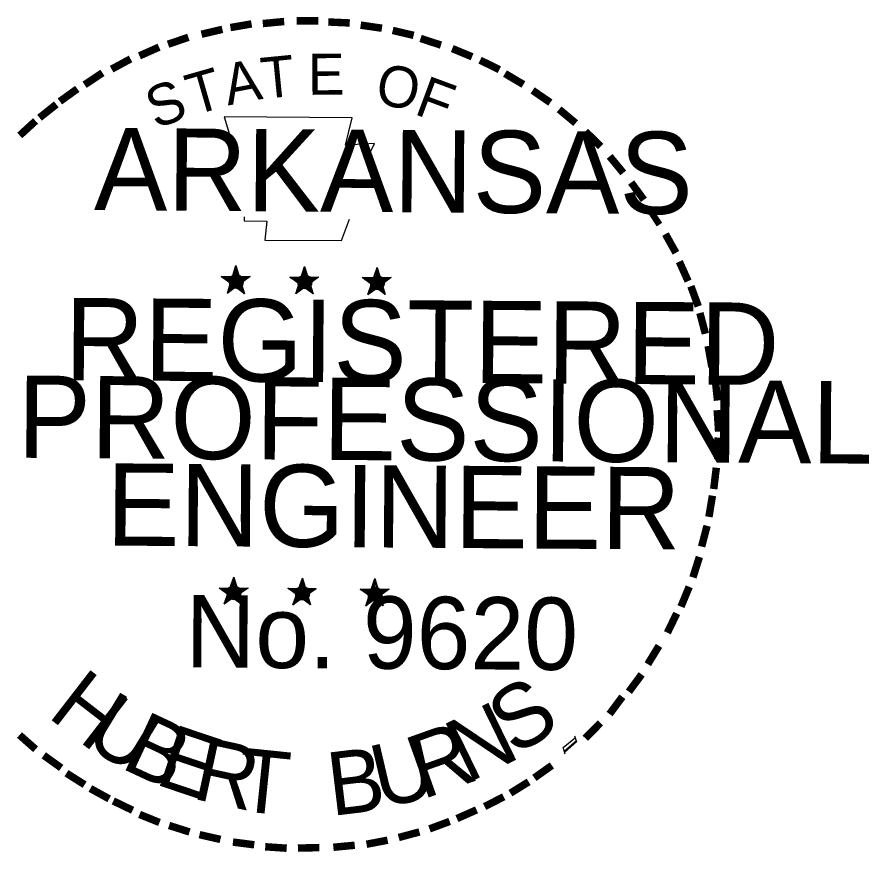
# Model space of a CAD drawing. Extents: x 309389.3 to 309420.2, y 336441.4 to 336461.2.
# Drawn here: x 309416.82 to 309420.237, y 336442.278 to 336445.626 of the extents above; entities that cross this region are included whole.
import ezdxf

# ---------------------------------------------------------------- set-up
doc = ezdxf.new("R2010")
doc.units = 0
doc.layers.add('R_Temp Easement', color=7, linetype='Continuous')

msp = doc.modelspace()

# ---------------------------------------------------------------- linework, layer by layer
at = {"layer": 'R_Temp Easement'}
for p, q in [((309417.6985, 336444.63), (309417.6904, 336444.5853)), ((309417.6985, 336444.63), (309417.6904, 336444.5893)), ((309417.6985, 336444.63), (309417.6944, 336444.5893)), ((309417.6985, 336444.5669), (309417.6985, 336444.63)), ((309417.6985, 336444.63), (309417.7087, 336444.5853)), ((309417.6985, 336444.63), (309417.7067, 336444.5893)), ((309417.6985, 336444.63), (309417.7005, 336444.5893)), ((309417.9732, 336444.626), (309417.9651, 336444.5832)), ((309417.9732, 336444.626), (309417.9651, 336444.5853)), ((309417.9732, 336444.626), (309417.9671, 336444.5853)), ((309417.9732, 336444.5669), (309417.9732, 336444.626)), ((309417.9732, 336444.626), (309417.9834, 336444.5832)), ((309417.9732, 336444.626), (309417.9814, 336444.5853)), ((309417.9732, 336444.626), (309417.9753, 336444.5853)), ((309418.2642, 336444.6219), (309418.2541, 336444.5832)), ((309418.2642, 336444.6219), (309418.2602, 336444.5812)), ((309418.2642, 336444.6219), (309418.2602, 336444.5812)), ((309418.2642, 336444.5608), (309418.2642, 336444.6219)), ((309418.2642, 336444.6219), (309418.2765, 336444.5812)), ((309418.2642, 336444.6219), (309418.2724, 336444.5812)), ((309418.2642, 336444.6219), (309418.2683, 336444.5812)), ((309417.6395, 336444.5853), (309417.6985, 336444.5669)), ((309417.6395, 336444.5853), (309417.6822, 336444.5832)), ((309417.6395, 336444.5853), (309417.6822, 336444.5812)), ((309417.6395, 336444.5853), (309417.6782, 336444.5751)), ((309417.6395, 336444.5853), (309417.6782, 336444.569)), ((309417.6395, 336444.5853), (309417.6782, 336444.5669)), ((309417.6395, 336444.5853), (309417.6782, 336444.5608)), ((309417.6639, 336444.5181), (309417.6985, 336444.5669)), ((309417.6639, 336444.5181), (309417.6782, 336444.5649)), ((309417.7555, 336444.5853), (309417.6985, 336444.5669)), ((309417.7331, 336444.5161), (309417.6985, 336444.5669)), ((309417.7555, 336444.5853), (309417.7026, 336444.5812)), ((309417.7555, 336444.5853), (309417.7087, 336444.5771)), ((309417.7555, 336444.5853), (309417.7087, 336444.573)), ((309417.7331, 336444.5161), (309417.7087, 336444.5649)), ((309417.7331, 336444.5161), (309417.7148, 336444.5669)), ((309417.7555, 336444.5853), (309417.7168, 336444.573)), ((309417.7555, 336444.5853), (309417.7229, 336444.569)), ((309417.7555, 336444.5853), (309417.725, 336444.5669)), ((309417.9142, 336444.5832), (309417.9732, 336444.5669)), ((309417.9142, 336444.5832), (309417.957, 336444.5812)), ((309417.9142, 336444.5832), (309417.957, 336444.5771)), ((309417.9142, 336444.5832), (309417.957, 336444.5751)), ((309417.9142, 336444.5832), (309417.9549, 336444.5669)), ((309417.9142, 336444.5832), (309417.9549, 336444.5649)), ((309417.9142, 336444.5832), (309417.9549, 336444.5588)), ((309417.9386, 336444.5161), (309417.9732, 336444.5669)), ((309418.0302, 336444.5832), (309417.9732, 336444.5669)), ((309418.0078, 336444.5161), (309417.9732, 336444.5669)), ((309418.0302, 336444.5832), (309417.9793, 336444.5812)), ((309418.0302, 336444.5832), (309417.9834, 336444.5751)), ((309418.0302, 336444.5832), (309417.9834, 336444.573)), ((309418.0078, 336444.5161), (309417.9834, 336444.5649)), ((309418.0078, 336444.5161), (309417.9895, 336444.5649)), ((309418.0302, 336444.5832), (309417.9916, 336444.569)), ((309418.0302, 336444.5832), (309417.9977, 336444.5669)), ((309418.0302, 336444.5832), (309417.9997, 336444.5649)), ((309418.2052, 336444.5812), (309418.2642, 336444.5608)), ((309418.2052, 336444.5812), (309418.252, 336444.5751)), ((309418.2052, 336444.5812), (309418.248, 336444.573)), ((309418.2052, 336444.5812), (309418.248, 336444.569)), ((309418.2052, 336444.5812), (309418.2459, 336444.5649)), ((309418.2052, 336444.5812), (309418.2459, 336444.5588)), ((309418.2052, 336444.5812), (309418.2459, 336444.5588)), ((309418.3212, 336444.5812), (309418.2642, 336444.5608)), ((309418.3212, 336444.5812), (309418.2703, 336444.5751)), ((309418.3212, 336444.5812), (309418.2765, 336444.573)), ((309418.3212, 336444.5812), (309418.2765, 336444.5669)), ((309418.3212, 336444.5812), (309418.2846, 336444.5649)), ((309418.3212, 336444.5812), (309418.2866, 336444.5649)), ((309418.3212, 336444.5812), (309418.2927, 336444.5608)), ((309417.6639, 336444.5181), (309417.6822, 336444.5588)), ((309417.6639, 336444.5181), (309417.6843, 336444.5568)), ((309417.6639, 336444.5181), (309417.6904, 336444.5527)), ((309417.6639, 336444.5181), (309417.6985, 336444.5527)), ((309417.6639, 336444.5181), (309417.6985, 336444.5486)), ((309417.7331, 336444.5161), (309417.6985, 336444.5527)), ((309417.7331, 336444.5161), (309417.6985, 336444.5486)), ((309417.7331, 336444.5161), (309417.7026, 336444.5527)), ((309417.7331, 336444.5161), (309417.7087, 336444.5588)), ((309417.9386, 336444.5161), (309417.957, 336444.5608)), ((309417.9386, 336444.5161), (309417.957, 336444.5588)), ((309417.9386, 336444.5161), (309417.959, 336444.5568)), ((309417.9386, 336444.5161), (309417.9651, 336444.5507)), ((309417.9386, 336444.5161), (309417.9732, 336444.5507)), ((309417.9386, 336444.5161), (309417.9732, 336444.5486)), ((309418.0078, 336444.5161), (309417.9732, 336444.5507)), ((309418.0078, 336444.5161), (309417.9732, 336444.5486)), ((309418.0078, 336444.5161), (309417.9793, 336444.5507)), ((309418.0078, 336444.5161), (309417.9834, 336444.5568)), ((309418.2276, 336444.514), (309418.2642, 336444.5608)), ((309418.2276, 336444.514), (309418.248, 336444.5588)), ((309418.2276, 336444.514), (309418.252, 336444.5527)), ((309418.2276, 336444.514), (309418.252, 336444.5507)), ((309418.2276, 336444.514), (309418.2642, 336444.5507)), ((309418.2276, 336444.514), (309418.2602, 336444.5486)), ((309418.2276, 336444.514), (309418.2683, 336444.5425)), ((309418.2968, 336444.514), (309418.2642, 336444.5608)), ((309418.2968, 336444.514), (309418.2642, 336444.5507)), ((309418.2968, 336444.514), (309418.2642, 336444.5425)), ((309418.2968, 336444.514), (309418.2703, 336444.5486)), ((309418.2968, 336444.514), (309418.2765, 336444.5588)), ((309418.2968, 336444.514), (309418.2765, 336444.5527)), ((309418.2968, 336444.514), (309418.2805, 336444.5588)), ((309417.6904, 336443.3805), (309417.6782, 336443.3398)), ((309417.6904, 336443.3805), (309417.6822, 336443.3358)), ((309417.6904, 336443.3805), (309417.6843, 336443.3358)), ((309417.6904, 336443.3174), (309417.6904, 336443.3805)), ((309417.6904, 336443.3805), (309417.6985, 336443.3358)), ((309417.6904, 336443.3805), (309417.6985, 336443.3358)), ((309417.6904, 336443.3805), (309417.6904, 336443.3358)), ((309417.9651, 336443.3765), (309417.9549, 336443.3358)), ((309417.9651, 336443.3765), (309417.957, 336443.3358)), ((309417.9651, 336443.3765), (309417.959, 336443.3358)), ((309417.9651, 336443.3174), (309417.9651, 336443.3765)), ((309417.9651, 336443.3765), (309417.9732, 336443.3337)), ((309417.9651, 336443.3765), (309417.9732, 336443.3337)), ((309417.9651, 336443.3765), (309417.9651, 336443.3358)), ((309418.2561, 336443.3744), (309418.2459, 336443.3317)), ((309418.2561, 336443.3744), (309418.248, 336443.3317)), ((309418.2561, 336443.3744), (309418.252, 336443.3317)), ((309418.2561, 336443.3113), (309418.2561, 336443.3744)), ((309418.2561, 336443.3744), (309418.2642, 336443.3317)), ((309418.2561, 336443.3744), (309418.2642, 336443.3317)), ((309418.2561, 336443.3744), (309418.2561, 336443.3317)), ((309417.6314, 336443.3358), (309417.6904, 336443.3174)), ((309417.6314, 336443.3358), (309417.6741, 336443.3337)), ((309417.6314, 336443.3358), (309417.6721, 336443.3276)), ((309417.6314, 336443.3358), (309417.6721, 336443.3276)), ((309417.6314, 336443.3358), (309417.6721, 336443.3195)), ((309417.6314, 336443.3358), (309417.6721, 336443.3174)), ((309417.6314, 336443.3358), (309417.6721, 336443.3154)), ((309417.7474, 336443.3358), (309417.6904, 336443.3174)), ((309417.7474, 336443.3358), (309417.6944, 336443.3337)), ((309417.7474, 336443.3358), (309417.6985, 336443.3276)), ((309417.7474, 336443.3358), (309417.6985, 336443.3256)), ((309417.7474, 336443.3358), (309417.7067, 336443.3236)), ((309417.7474, 336443.3358), (309417.7107, 336443.3195)), ((309417.7474, 336443.3358), (309417.7148, 336443.3174)), ((309417.9061, 336443.3358), (309417.9651, 336443.3174)), ((309417.9061, 336443.3358), (309417.9488, 336443.3317)), ((309417.9061, 336443.3358), (309417.9488, 336443.3276)), ((309417.9061, 336443.3358), (309417.9488, 336443.3256)), ((309417.9061, 336443.3358), (309417.9468, 336443.3195)), ((309417.9061, 336443.3358), (309417.9468, 336443.3154)), ((309417.9061, 336443.3358), (309417.9468, 336443.3113)), ((309418.02, 336443.3337), (309417.9651, 336443.3174)), ((309418.02, 336443.3337), (309417.9712, 336443.3337)), ((309418.02, 336443.3337), (309417.9732, 336443.3256)), ((309418.02, 336443.3337), (309417.9732, 336443.3256)), ((309418.02, 336443.3337), (309417.9814, 336443.3195)), ((309418.02, 336443.3337), (309417.9875, 336443.3174)), ((309418.02, 336443.3337), (309417.9895, 336443.3154)), ((309418.1971, 336443.3317), (309418.2561, 336443.3113)), ((309418.1971, 336443.3317), (309418.2398, 336443.3276)), ((309418.1971, 336443.3317), (309418.2398, 336443.3236)), ((309418.1971, 336443.3317), (309418.2378, 336443.3195)), ((309418.1971, 336443.3317), (309418.2378, 336443.3154)), ((309418.1971, 336443.3317), (309418.2358, 336443.3113)), ((309418.1971, 336443.3317), (309418.2358, 336443.3073)), ((309418.3131, 336443.3317), (309418.2561, 336443.3113)), ((309418.3131, 336443.3317), (309418.2622, 336443.3276)), ((309418.3131, 336443.3317), (309418.2642, 336443.3236)), ((309418.3131, 336443.3317), (309418.2642, 336443.3195)), ((309418.3131, 336443.3317), (309418.2765, 336443.3174)), ((309418.3131, 336443.3317), (309418.2785, 336443.3113)), ((309418.3131, 336443.3317), (309418.2805, 336443.3113)), ((309417.6517, 336443.2727), (309417.6904, 336443.3174)), ((309417.6517, 336443.2727), (309417.6721, 336443.3174)), ((309417.6517, 336443.2727), (309417.6741, 336443.3093)), ((309417.6517, 336443.2727), (309417.6761, 336443.3093)), ((309417.6517, 336443.2727), (309417.6904, 336443.3073)), ((309417.6517, 336443.2727), (309417.6822, 336443.3032)), ((309417.6517, 336443.2727), (309417.6904, 336443.3012)), ((309417.7229, 336443.2686), (309417.6863, 336443.3012)), ((309417.7229, 336443.2686), (309417.6904, 336443.3174)), ((309417.7229, 336443.2686), (309417.6904, 336443.3032)), ((309417.7229, 336443.2686), (309417.6924, 336443.3032)), ((309417.7229, 336443.2686), (309417.6985, 336443.3174)), ((309417.7229, 336443.2686), (309417.6985, 336443.3093)), ((309417.7229, 336443.2686), (309417.7067, 336443.3174)), ((309417.9264, 336443.2686), (309417.9651, 336443.3174)), ((309417.9264, 336443.2686), (309417.9488, 336443.3154)), ((309417.9264, 336443.2686), (309417.9488, 336443.3073)), ((309417.9264, 336443.2686), (309417.9509, 336443.3073)), ((309417.9264, 336443.2686), (309417.957, 336443.3032)), ((309417.9264, 336443.2686), (309417.9651, 336443.3032)), ((309417.9264, 336443.2686), (309417.9651, 336443.2991)), ((309417.9977, 336443.2686), (309417.9631, 336443.2991)), ((309417.9977, 336443.2686), (309417.9651, 336443.3174)), ((309417.9977, 336443.2686), (309417.9651, 336443.3032)), ((309417.9977, 336443.2686), (309417.9671, 336443.3032)), ((309417.9977, 336443.2686), (309417.9732, 336443.3154)), ((309417.9977, 336443.2686), (309417.9732, 336443.3093)), ((309417.9977, 336443.2686), (309417.9814, 336443.3154)), ((309418.2195, 336443.2645), (309418.2561, 336443.3113)), ((309418.2195, 336443.2645), (309418.2378, 336443.3113)), ((309418.2195, 336443.2645), (309418.2398, 336443.3032)), ((309418.2195, 336443.2645), (309418.2439, 336443.3032)), ((309418.2195, 336443.2645), (309418.248, 336443.2991)), ((309418.2195, 336443.2645), (309418.2541, 336443.2991)), ((309418.2887, 336443.2645), (309418.2541, 336443.2991)), ((309418.2887, 336443.2645), (309418.2561, 336443.3113)), ((309418.2887, 336443.2645), (309418.2602, 336443.2991)), ((309418.2887, 336443.2645), (309418.2642, 336443.3032)), ((309418.2887, 336443.2645), (309418.2683, 336443.3113)), ((309418.2887, 336443.2645), (309418.2703, 336443.3113)), ((309418.2195, 336443.2645), (309418.2561, 336443.2951)), ((309418.2887, 336443.2645), (309418.2541, 336443.2951))]:
    msp.add_line(p, q, dxfattribs=at)
for points in [[(309417.6517, 336445.2263), (309417.6924, 336445.0879)], [(309418.2296, 336445.0696), (309418.2541, 336445.1184), (309418.1381, 336445.1123), (309418.1645, 336445.2222), (309417.6517, 336445.2263)], [(309417.7311, 336444.8254), (309417.7311, 336444.8091), (309417.8226, 336444.8071), (309417.8145, 336444.7318), (309418.1218, 336444.7297), (309418.1544, 336444.8152)], [(309417.6985, 336444.63), (309417.7331, 336444.5161), (309417.6395, 336444.5853), (309417.7555, 336444.5853), (309417.6639, 336444.5181), (309417.6985, 336444.63)], [(309417.9732, 336444.626), (309418.0078, 336444.5161), (309417.9142, 336444.5832), (309418.0302, 336444.5832), (309417.9386, 336444.5161), (309417.9732, 336444.626)], [(309418.2642, 336444.6219), (309418.2968, 336444.514), (309418.2052, 336444.5812), (309418.3212, 336444.5812), (309418.2276, 336444.514), (309418.2642, 336444.6219)], [(309417.6904, 336443.3805), (309417.7229, 336443.2686), (309417.6314, 336443.3358), (309417.7474, 336443.3358), (309417.6517, 336443.2727), (309417.6904, 336443.3805)], [(309417.9651, 336443.3765), (309417.9977, 336443.2686), (309417.9061, 336443.3358), (309418.02, 336443.3337), (309417.9264, 336443.2686), (309417.9651, 336443.3765)], [(309418.2561, 336443.3744), (309418.2887, 336443.2645), (309418.1971, 336443.3317), (309418.3131, 336443.3317), (309418.2195, 336443.2645), (309418.2561, 336443.3744)], [(309419.0192, 336442.6703), (309419.0111, 336442.6968), (309419.0599, 336442.7375)], [(309419.0559, 336442.7436), (309419.064, 336442.7192), (309419.0152, 336442.6764)], [(309419.064, 336442.7232), (309419.0152, 336442.6805)], [(309419.064, 336442.7192), (309419.0172, 336442.6785)]]:
    msp.add_lwpolyline(points, dxfattribs=at)
for centre, radius in [((309417.6995, 336444.5659), 0.0284), ((309417.6995, 336444.5659), 0.0257), ((309417.6995, 336444.5659), 0.0238), ((309417.6995, 336444.5659), 0.0219), ((309417.6995, 336444.5659), 0.0191), ((309417.6995, 336444.5659), 0.0177), ((309417.6995, 336444.5659), 0.0163), ((309417.6995, 336444.5659), 0.0141), ((309417.6995, 336444.5659), 0.0123), ((309417.6995, 336444.5659), 0.0102), ((309417.6995, 336444.5659), 0.00817), ((309417.6995, 336444.5659), 0.00609), ((309417.6995, 336444.5659), 0.00489), ((309417.6995, 336444.5659), 0.00238), ((309417.9747, 336444.564), 0.0284), ((309417.9747, 336444.564), 0.0257), ((309417.9747, 336444.564), 0.0238), ((309417.9747, 336444.564), 0.0219), ((309417.9747, 336444.564), 0.0191), ((309417.9747, 336444.564), 0.0177), ((309417.9747, 336444.564), 0.0163), ((309417.9747, 336444.564), 0.0141), ((309417.9747, 336444.564), 0.0123), ((309417.9747, 336444.564), 0.0102), ((309417.9747, 336444.564), 0.00817), ((309417.9747, 336444.564), 0.00609), ((309417.9747, 336444.564), 0.00489), ((309417.9747, 336444.564), 0.00238), ((309418.266, 336444.5601), 0.0284), ((309418.266, 336444.5601), 0.0257), ((309418.266, 336444.5601), 0.0238), ((309418.266, 336444.5601), 0.0219), ((309418.266, 336444.5601), 0.0191), ((309418.266, 336444.5601), 0.0177), ((309418.266, 336444.5601), 0.0163), ((309418.266, 336444.5601), 0.0141), ((309418.266, 336444.5601), 0.0123), ((309418.266, 336444.5601), 0.0102), ((309418.266, 336444.5601), 0.00817), ((309418.266, 336444.5601), 0.00609), ((309418.266, 336444.5601), 0.00489), ((309418.266, 336444.5601), 0.00238), ((309417.6902, 336443.3174), 0.0284), ((309417.6902, 336443.3174), 0.0257), ((309417.6902, 336443.3174), 0.0238), ((309417.6902, 336443.3174), 0.0219), ((309417.6902, 336443.3174), 0.0191), ((309417.6902, 336443.3174), 0.0177), ((309417.6902, 336443.3174), 0.0163), ((309417.6902, 336443.3174), 0.0141), ((309417.9654, 336443.3155), 0.0284), ((309417.9654, 336443.3155), 0.0257), ((309417.9654, 336443.3155), 0.0238), ((309417.9654, 336443.3155), 0.0219), ((309417.9654, 336443.3155), 0.0191), ((309417.9654, 336443.3155), 0.0177), ((309417.9654, 336443.3155), 0.0163), ((309418.2567, 336443.3115), 0.0284), ((309418.2567, 336443.3115), 0.0257), ((309418.2567, 336443.3115), 0.0238), ((309418.2567, 336443.3115), 0.0219), ((309417.6902, 336443.3174), 0.0123), ((309417.6902, 336443.3174), 0.0102), ((309417.6902, 336443.3174), 0.00817), ((309417.6902, 336443.3174), 0.00609), ((309417.6902, 336443.3174), 0.00489), ((309417.6902, 336443.3174), 0.00238), ((309417.9654, 336443.3155), 0.0141), ((309417.9654, 336443.3155), 0.0123), ((309417.9654, 336443.3155), 0.0102), ((309417.9654, 336443.3155), 0.00817), ((309417.9654, 336443.3155), 0.00609), ((309417.9654, 336443.3155), 0.00489), ((309417.9654, 336443.3155), 0.00238), ((309418.2567, 336443.3115), 0.0191), ((309418.2567, 336443.3115), 0.0177), ((309418.2567, 336443.3115), 0.0163), ((309418.2567, 336443.3115), 0.0141), ((309418.2567, 336443.3115), 0.0123), ((309418.2567, 336443.3115), 0.0102), ((309418.2567, 336443.3115), 0.00817), ((309418.2567, 336443.3115), 0.00609), ((309418.2567, 336443.3115), 0.00489), ((309418.2567, 336443.3115), 0.00238)]:
    msp.add_circle(centre, radius, dxfattribs=at)

# ---------------------------------------------------------------- texts
for s, height, rotation, p in [('-', 0.2637, 5.4992, (309417.8003, 336445.4969)), ('-', 0.2637, 359.7886, (309417.9264, 336445.5091)), ('-', 0.2638, 357.3454, (309418.0485, 336445.5051)), ('-', 0.2637, 13.2326, (309417.5683, 336445.4542)), ('-', 0.2638, 9.8217, (309417.6782, 336445.4807)), ('-', 0.2638, 351.7641, (309418.1686, 336445.4949)), ('-', 0.2638, 346.8073, (309418.2887, 336445.4766)), ('-', 0.2637, 18.7785, (309417.4441, 336445.4155)), ('-', 0.2638, 341.9386, (309418.3924, 336445.4481)), ('-', 0.2638, 23.9096, (309417.3383, 336445.3708)), ('-', 0.2638, 337.4575, (309418.5125, 336445.4115)), ('-', 0.2638, 28.3942, (309417.2345, 336445.3199)), ('T', 0.1648, 5.6252, (309417.8064, 336445.2975)), ('E', 0.1649, 0.4347, (309417.9875, 336445.3138)), ('-', 0.2638, 333.7235, (309418.6183, 336445.3687)), ('T', 0.1648, 16.006, (309417.5276, 336445.2303)), ('A', 0.1649, 10.8156, (309417.666, 336445.271)), ('O', 0.1648, 350.0539, (309418.252, 336445.2792)), ('-', 0.2638, 33.666, (309417.1348, 336445.2609)), ('F', 0.1648, 339.6731, (309418.4087, 336445.2385)), ('-', 0.2637, 329.2433, (309418.7119, 336445.3199)), ('-', 0.2637, 35.8341, (309417.0392, 336445.1958)), ('S', 0.1648, 21.1964, (309417.377, 336445.1754)), ('-', 0.2637, 325.4651, (309418.8178, 336445.2568)), ('-', 0.2637, 38.5531, (309416.9618, 336445.1327)), ('-', 0.2638, 320.1321, (309418.9175, 336445.1876)), ('-', 0.2637, 42.5646, (309416.8886, 336445.0655)), ('ARKANSAS', 0.32974, 359.6024, (309417.1287, 336444.8518)), ('-', 0.2638, 315.181, (309419.0172, 336445.1062)), ('-', 0.2637, 309.4821, (309419.1088, 336445.0146)), ('-', 0.2637, 306.2546, (309419.1922, 336444.9149)), ('-', 0.2308, 303.2777, (309419.2736, 336444.8193)), ('-', 0.2638, 299.2708, (309419.3245, 336444.7196)), ('-', 0.2637, 294.2652, (309419.3774, 336444.6178)), ('-', 0.2637, 290.1752, (309419.4222, 336444.5262)), ('REGISTERED', 0.32974, 359.6024, (309417.0107, 336444.1701)), ('-', 0.2638, 284.7257, (309419.4568, 336444.4286)), ('-', 0.2638, 280.1517, (309419.4893, 336444.3044)), ('PROFESSIONAL', 0.329743, 359.6024, (309416.8214, 336443.8588)), ('-', 0.2638, 276.1986, (309419.5178, 336444.1783)), ('-', 0.2638, 273.9325, (309419.5259, 336444.0582)), ('-', 0.2637, 269.5431, (309419.53, 336443.9564)), ('ENGINEER', 0.32974, 359.6024, (309417.1776, 336443.5067)), ('-', 0.2637, 263.1196, (309419.5259, 336443.8465)), ('-', 0.2638, 260.5977, (309419.5117, 336443.7387)), ('-', 0.2637, 255.365, (309419.4934, 336443.6268)), ('-', 0.2638, 252.4705, (309419.4649, 336443.5067)), ('-', 0.2638, 247.4911, (309419.4283, 336443.3948)), ('No. 9620', 0.29016, 359.6024, (309417.495, 336443.0183)), ('-', 0.2638, 244.2221, (309419.3815, 336443.293)), ('-', 0.2638, 238.6736, (309419.3163, 336443.1709)), ('H', 0.254, 322.2636, (309416.9374, 336442.8229)), ('-', 0.2638, 233.4476, (309419.2533, 336443.0631)), ('S', 0.254, 32.3337, (309418.8178, 336442.6601)), ('U', 0.254, 328.6336, (309417.0799, 336442.7131)), ('-', 0.2638, 233.4476, (309419.1759, 336442.9735)), ('N', 0.254, 25.9637, (309418.6265, 336442.5523)), ('B', 0.254, 335.0036, (309417.2305, 336442.6174)), ('E', 0.254, 341.3736, (309417.3668, 336442.5523)), ('R', 0.254, 19.5937, (309418.4454, 336442.4872)), ('-', 0.2637, 225.3677, (309419.0986, 336442.8779)), ('-', 0.2638, 138.5362, (309416.9741, 336442.7558)), ('R', 0.254, 347.7436, (309417.5174, 336442.4933)), ('U', 0.254, 13.2237, (309418.2765, 336442.4505)), ('T', 0.254, 354.1136, (309417.6944, 336442.4444)), ('B', 0.254, 6.8537, (309418.0811, 336442.422)), ('-', 0.2637, 144.2487, (309417.0697, 336442.6886)), ('-', 0.2637, 215.3387, (309418.9195, 336442.7171)), ('-', 0.2638, 147.6922, (309417.1592, 336442.6255)), ('-', 0.2637, 151.1728, (309417.2528, 336442.5726)), ('-', 0.2638, 211.8515, (309418.832, 336442.654)), ('-', 0.2638, 206.9592, (309418.7404, 336442.5971)), ('-', 0.2637, 154.2026, (309417.3424, 336442.5299)), ('-', 0.2637, 203.854, (309418.6366, 336442.5462)), ('-', 0.2638, 158.1636, (309417.4441, 336442.4851)), ('-', 0.2638, 200.3208, (309418.5349, 336442.5014)), ('-', 0.2638, 162.4007, (309417.5581, 336442.4505)), ('-', 0.2638, 167.1579, (309417.6741, 336442.4241)), ('-', 0.2638, 190.8882, (309418.3029, 336442.4282)), ('-', 0.2637, 195.0767, (309418.423, 336442.4607)), ('-', 0.2638, 172.7179, (309417.8003, 336442.4058)), ('-', 0.2638, 176.1207, (309417.9244, 336442.3936)), ('-', 0.2638, 181.1942, (309418.0465, 336442.3976)), ('-', 0.2637, 185.4191, (309418.1808, 336442.4078))]:
    msp.add_text(s, height=height, rotation=rotation, dxfattribs=at).set_placement(p)

doc.saveas('drawing.dxf')
